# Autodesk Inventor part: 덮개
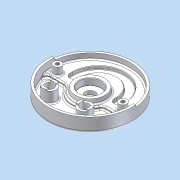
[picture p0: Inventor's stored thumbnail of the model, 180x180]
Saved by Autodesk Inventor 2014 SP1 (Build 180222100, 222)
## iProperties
Company: 한국ATC센터
Created: 2015-04
Part Number: 덮개
Document SubType Name: Modeling
Designer: KYOUNG IL JANG
Density: 2.71 g/cm^3
Material: 알루미늄-6061
Appearance: 매끄러움 - 흰색
Author: KYOUNG IL JANG
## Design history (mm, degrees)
sketch "스케치1"
  geometry: L1 (-59, -19)-(-59, 19); L2 (59, 19)-(59, -19); L3 (-41, 19)-(-41, -19); L4 (41, -19)-(41, 19); L5 (59, 5)-(41, 5); L6 (-41, 5)-(-59, 5); C1 r 90 at (0, 0); C2 r 95 at (0, 0); A1 r 59 centre (0, 19) between (59, 19) and (-59, 19); A2 r 59 centre (0, -19) between (-59, -19) and (59, -19); A3 r 41 centre (0, -19) between (-41, -19) and (41, -19); A4 r 41 centre (0, 19) between (41, 19) and (-41, 19); 2 further points
  constraints: 12 end point, 8 point on circle, 6 centre point, 4 point on line, 4 tangent, 2 parallel, 2 perpendicular, 1 coincident, 1 collinear, 1 horizontal alignment, 1 midpoint, 1 vertical, 1 vertical alignment, 3 other
  dimensions: "d2" = 180 diameter of C1; "d3" = 156 dimension on A2 A1; "d4" = 118 distance between parallel lines of L2 L1; "d5" = 18 distance between parallel lines of L2 L4; "d8" = 190 diameter of C2; "d121" = 5 distance from line of L5 point (0, 0)
extrude "돌출1" new body sketch "스케치1" distance "d6" = 14; taper "d7" = 0 deg
extrude "돌출2" join sketch "스케치1" distance "d9" = 13; taper "d10" = 0 deg
extrude "돌출3" cut sketch "스케치1" distance "d11" = 7; taper "d12" = 0 deg
sketch "스케치2"
  geometry: C1 r 11.5 at (0, 0); 1 further point
  constraints: 1 centre point, 1 coincident
  dimensions: "d13" = 23 diameter of C1
extrude "돌출4" cut sketch "스케치2" stored distance "d14" = 7; taper "d15" = 0 deg
fillet "모깎기1"
fillet "모깎기2"
sketch "스케치3"
  geometry: L1 (-89.658, 7.844)-(-94.638, 8.28); L2 (89.658, 7.844)-(94.638, 8.28); L3 (0, 0)-(0, -90); A1 r 95 centre (0, 0) between (-94.638, 8.28) and (94.638, 8.28) reference; A2 r 90 centre (0, 0) between (-89.658, 7.844) and (89.658, 7.844) reference; 1 further point
  constraints: 6 end point, 5 point on circle, 1 point on line, 1 vertical, 1 other
  dimensions: "d16" = 190 deg dimension on L2 L1
extrude "돌출5" join sketch "스케치3" distance "d17" = 5; taper "d18" = 0 deg
hole "구멍1" diameter "d21" = 50; stored, may be unused: countersink angle "d25" = 90 deg, drill point angle "d27" = 0 deg; dims "d19" = 10, "d20" = 10, "d22" = 6, "d23" = 4, "d24" = 2, "d26" = 5
fillet "모깎기3" dims "d28" = 0.3
fillet "모깎기5" dims "d30" = 3
sketch "스케치4"
  geometry: C1 r 35 at (0, 0); C2 r 25 at (0, 0); 1 further point
  constraints: 2 centre point, 1 coincident
  dimensions: "d32" = 70 diameter of C1 (derived); "d36" = 10 radial gap between concentric circles of C1 C2
extrude "돌출6" join sketch "스케치4" distance "d33" = 10; taper "d34" = 0 deg
feature "면 기울기2" dims angle "d37" = 10 deg
chamfer "모따기1" distance "d39" = 1; stored, may be unused: second distance "d40" = 2, angle "d41" = 45 deg
fillet "모깎기7" dims "d42" = 5
sketch "스케치5"
  geometry: L1 (-40.249, -12)-(-89.196, -12); L2 (40.249, -12)-(89.196, -12); A1 r 90 centre (0, 0) between (-89.196, -12) and (89.196, -12) reference; A2 r 42 centre (0, 0) between (-40.249, -12) and (40.249, -12); 1 further point
  constraints: 4 end point, 4 point on circle, 1 centre point, 1 collinear, 1 horizontal, 1 point on line
  dimensions: "d43" = 48 radial gap between concentric circles of A1 A2; "d44" = 12 distance from line of point (0, 0) L1
extrude "돌출7" cut sketch "스케치5" stored distance "d45" = 10; taper "d46" = 0 deg
fillet "모깎기8" dims "d47" = 10
chamfer "모따기2" distance "d49" = 1; stored, may be unused: second distance "d50" = 2, angle "d51" = 45 deg
sketch "스케치8"
  geometry: C1 r 9 at (74, 0); C2 r 9 at (-74, 0); A1 r 74 centre (0, 0) between (74, 0) and (-74, 0); 1 further point
  constraints: 3 centre point, 2 horizontal alignment, 2 point on circle, 1 coincident, 1 equal radius
  dimensions: "d64" = 18 diameter of C1; "d65" = 148 diameter of A1
extrude "돌출9" join sketch "스케치8" stored distance "d66" = 5; taper "d67" = 0 deg
sketch "스케치11"
  geometry: C1 r 15 at (40, -52); C2 r 15 at (-40, -52); 1 further point
  constraints: 2 centre point, 1 equal radius, 1 horizontal alignment
  dimensions: "d82" = 52 vertical distance of point (0, 0) C1.centre; "d83" = 30 diameter of C1; "d84" = 80 distance of C2.centre C1.centre; "d85" = 40 horizontal distance of point (0, 0) C1.centre (= 0.5 x d84)
extrude "돌출10" join sketch "스케치11" stored distance "d86" = 10; taper "d87" = 0 deg
node "구멍3"
node "구멍5"
hole "구멍6" diameter "d92" = 20; stored, may be unused: countersink angle "d96" = 90 deg, drill point angle "d98" = 118 deg; dims "d90" = 10, "d91" = 10, "d93" = 6, "d94" = 4, "d95" = 2, "d97" = 8
hole "구멍7" diameter "d101" = 20; stored, may be unused: countersink angle "d105" = 90 deg, drill point angle "d107" = 118 deg; dims "d99" = 10, "d100" = 10, "d102" = 6, "d103" = 4, "d104" = 2, "d106" = 8
fillet "모깎기13" dims "d108" = 3
sketch "스케치13"
  geometry: L1 (-20.252, -58)-(-26, -58); L2 (-42, -58)-(-47.748, -58); L3 (-20.252, -46)-(-26, -46); L4 (-42, -46)-(-47.748, -46); L5 (-108, -65.748)-(-108, -60); L6 (-108, -44)-(-108, -38.252); L7 (-120, -44)-(-120, -38.252); L8 (-120, -60)-(-120, -65.748); A1 r 15 centre (-34, -52) between (-20.252, -58) and (-47.748, -58) reference; A2 r 10 centre (-34, -52) between (-26, -58) and (-42, -58) reference; A3 r 15 centre (-114, -52) between (-108, -65.748) and (-108, -38.252) reference; A4 r 10 centre (-114, -52) between (-108, -60) and (-108, -44) reference; 1 further point
  constraints: 16 end point, 16 point on circle, 3 equal length, 3 point on line, 2 collinear, 1 horizontal, 1 perpendicular
  dimensions: "d114" = 12 distance between parallel lines of L4 L2; "d115" = 6 distance from line of A1.centre L2 (= 0.5 x d114); "d116" = 12 distance between parallel lines of L8 L5 (= d114); "d117" = 6 distance from line of A3.centre L5 (= d115)
extrude "돌출12" join sketch "스케치13" distance "d118" = 3; taper "d119" = 0 deg
fillet "모깎기14" dims "d120" = 1
node "솔리드1"
sketch "스케치9"
  geometry: 1 further point
hole "구멍2" sketch "스케치9" diameter "d68" = 8.376; stored, may be unused: countersink angle "d72" = 90 deg, drill point angle "d74" = 120 deg; dims "d69" = 16, "d70" = 4, "d71" = 2, "d73" = 21
sketch "스케치10"
  geometry: 1 further point
hole "구멍4" sketch "스케치10" diameter "d75" = 8.376; stored, may be unused: countersink angle "d79" = 90 deg, drill point angle "d81" = 120 deg; dims "d76" = 16, "d77" = 4, "d78" = 2, "d80" = 21
